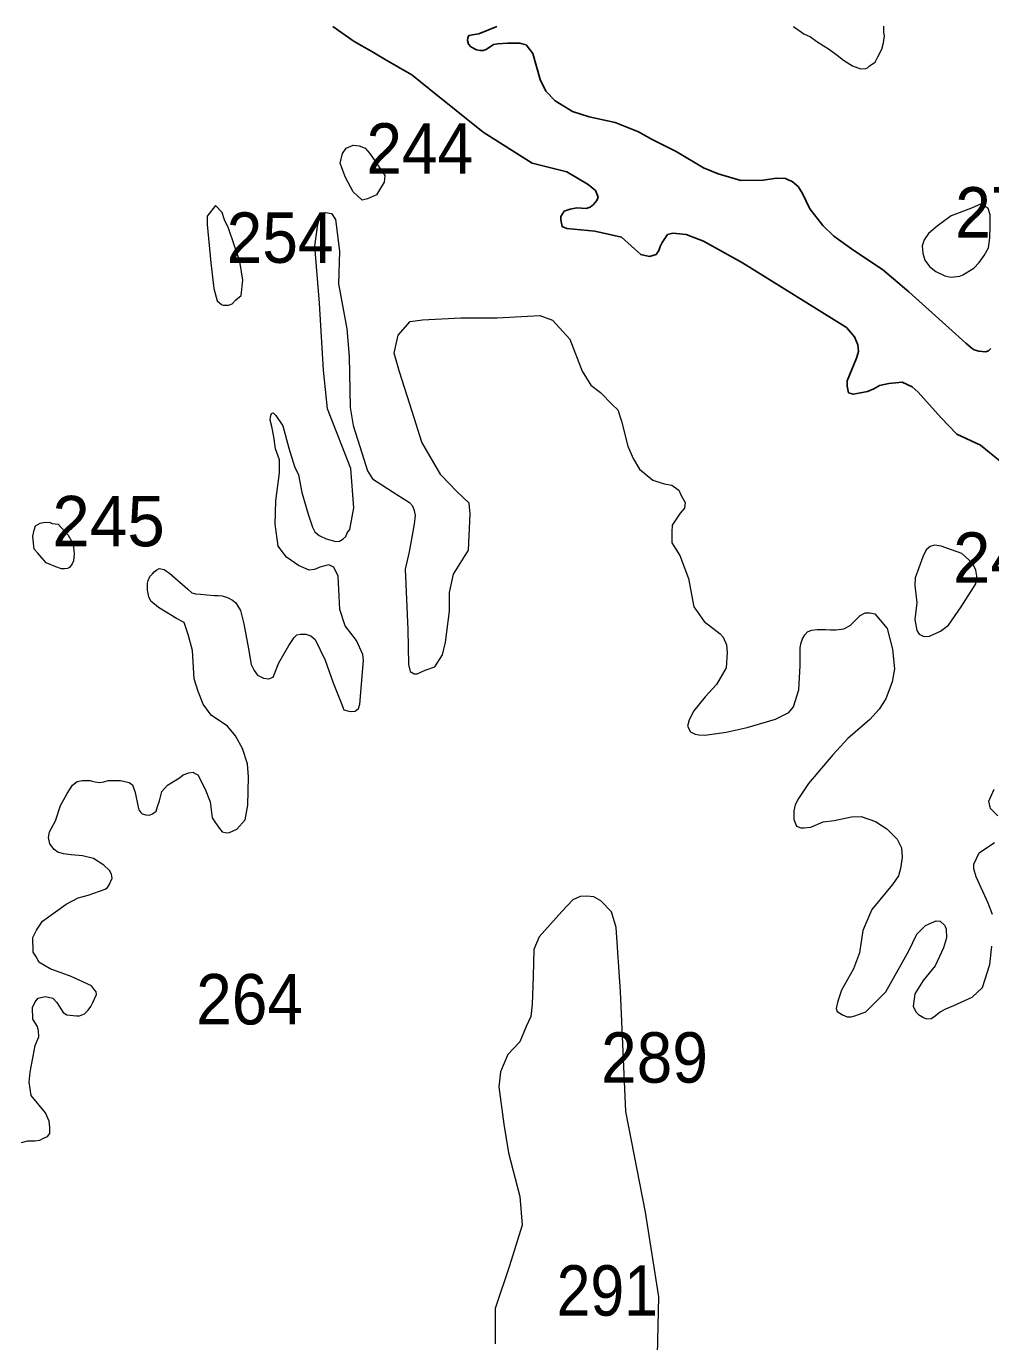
# Model space of a CAD drawing. Extents: x 445.4 to 500, y 8728.7 to 8784.
# Drawn here: x 476.604 to 479.664, y 8779.826 to 8784 of the extents above; entities that cross this region are included whole.
import ezdxf

# ---------------------------------------------------------------- set-up
doc = ezdxf.new("R2010")
doc.units = 0
doc.header["$LTSCALE"] = 0.064
doc.layers.add('1', color=7, linetype='Continuous', lineweight=25)
doc.layers.add('2', color=7, linetype='Continuous', lineweight=13)
doc.layers.add('21', color=7, linetype='Continuous')

msp = doc.modelspace()

# ---------------------------------------------------------------- linework, layer by layer
at = {"layer": '1'}
for points in [[(479.213, 8782.8368), (479.2087, 8782.858), (479.2087, 8782.8749), (479.2384, 8782.9468), (479.2447, 8782.968), (479.2426, 8782.9891), (479.232, 8783.0145), (479.2066, 8783.0441), (478.8763, 8783.2492), (478.7526, 8783.3183), (478.6975, 8783.3394), (478.6552, 8783.3436), (478.6382, 8783.3394), (478.6213, 8783.314), (478.6149, 8783.3013), (478.6107, 8783.2887), (478.6022, 8783.276), (478.6022, 8783.276), (478.5811, 8783.2696), (478.5535, 8783.276), (478.4921, 8783.3309), (478.4074, 8783.35), (478.3185, 8783.3584), (478.3037, 8783.3648), (478.2994, 8783.3859), (478.2994, 8783.3965), (478.31, 8783.4134), (478.3291, 8783.4198), (478.3503, 8783.424), (478.3799, 8783.4219), (478.3926, 8783.4261), (478.4032, 8783.4346), (478.4138, 8783.4473), (478.418, 8783.4578), (478.4095, 8783.479), (478.3863, 8783.498), (478.3185, 8783.5382), (478.2084, 8783.5657), (478.0531, 8783.6641), (477.8815, 8783.8016), (477.8265, 8783.846), (477.7418, 8783.8946), (477.6995, 8783.92), (477.6444, 8783.9517), (477.5759, 8783.999)], [(478.0963, 8783.9994), (478.0395, 8783.9765), (478.0184, 8783.9735), (478.0078, 8783.9712), (478.0041, 8783.9637), (478.0033, 8783.9546), (478.0071, 8783.9433), (478.0139, 8783.935), (478.032, 8783.9252), (478.0433, 8783.923), (478.0531, 8783.923), (478.0629, 8783.926), (478.0629, 8783.926), (478.0856, 8783.9426), (478.0999, 8783.9448), (478.1301, 8783.9471), (478.1512, 8783.9471), (478.1693, 8783.9471), (478.1769, 8783.9448), (478.1897, 8783.941), (478.2108, 8783.9139), (478.2342, 8783.831), (478.252, 8783.7943), (478.2814, 8783.7634), (478.3372, 8783.7302), (478.3893, 8783.7129), (478.4716, 8783.6948), (478.5463, 8783.6654), (478.5891, 8783.6409), (478.6653, 8783.6024), (478.7521, 8783.5512), (478.7989, 8783.5323), (478.8713, 8783.5112), (478.9415, 8783.512), (478.9844, 8783.518), (479.0131, 8783.5173), (479.0206, 8783.5135), (479.0342, 8783.5082), (479.0523, 8783.4917), (479.0667, 8783.4699), (479.09, 8783.4209), (479.1308, 8783.3682), (479.1655, 8783.3343), (479.2297, 8783.289), (479.3202, 8783.2287), (479.4037, 8783.1581), (479.5305, 8783.0435), (479.5852, 8782.9948), (479.6048, 8782.9782), (479.6108, 8782.9737), (479.6259, 8782.9691), (479.647, 8782.9676), (479.6569, 8782.9699), (479.6644, 8782.9774)], [(479.7458, 8782.5779), (479.6314, 8782.6709), (479.556, 8782.7057), (479.5052, 8782.7586), (479.4332, 8782.8389), (479.4141, 8782.8559), (479.3824, 8782.8707), (479.3612, 8782.8686), (479.34, 8782.8664), (479.3104, 8782.8601), (479.2934, 8782.8495), (479.2723, 8782.8411), (479.2511, 8782.8368), (479.2278, 8782.8326), (479.213, 8782.8368)]]:
    msp.add_lwpolyline(points, dxfattribs=at)
at = {"layer": '2'}
for points in [[(479.038, 8783.9999), (479.071, 8783.9757), (479.0921, 8783.9669), (479.1124, 8783.9524), (479.1524, 8783.9263), (479.177, 8783.9081), (479.1966, 8783.8928), (479.2257, 8783.8747), (479.2511, 8783.8652), (479.2678, 8783.8667), (479.2729, 8783.8681), (479.2794, 8783.8747), (479.2968, 8783.8863), (479.3056, 8783.903), (479.3186, 8783.9277), (479.3237, 8783.948), (479.3266, 8783.9698), (479.3244, 8783.98), (479.3245, 8784.0001)], [(477.4539, 8782.0606), (477.4621, 8782.0688), (477.4733, 8782.0719), (477.4908, 8782.0709), (477.5061, 8782.0658), (477.5205, 8782.0545), (477.5522, 8781.989), (477.5768, 8781.9174), (477.6024, 8781.8539), (477.6116, 8781.8314), (477.627, 8781.8273), (477.6362, 8781.8263), (477.6475, 8781.8273), (477.6578, 8781.8355), (477.6618, 8781.8498), (477.6677, 8781.9113), (477.6738, 8781.9891), (477.6718, 8782.0065), (477.6513, 8782.0515), (477.6154, 8782.0975), (477.5989, 8782.1494), (477.5928, 8782.2558), (477.5795, 8782.2845), (477.5631, 8782.2917), (477.5508, 8782.2886), (477.5354, 8782.2835), (477.5231, 8782.2783), (477.517, 8782.2763), (477.5016, 8782.2743), (477.4678, 8782.2896), (477.4293, 8782.3157), (477.4027, 8782.3505), (477.3934, 8782.42), (477.3955, 8782.4948), (477.4068, 8782.5828), (477.4069, 8782.6244), (477.3946, 8782.6592), (477.3885, 8782.6971), (477.3823, 8782.7308), (477.3772, 8782.7503), (477.3782, 8782.7605), (477.3813, 8782.7718), (477.3813, 8782.7718), (477.3864, 8782.7738), (477.3956, 8782.7656), (477.4171, 8782.7319), (477.4366, 8782.6612), (477.4551, 8782.6039), (477.4673, 8782.5773), (477.4776, 8782.521), (477.4982, 8782.4517), (477.5115, 8782.4108), (477.5187, 8782.3965), (477.533, 8782.3842), (477.5546, 8782.374), (477.5853, 8782.3658), (477.5976, 8782.3668), (477.6078, 8782.3729), (477.6171, 8782.3811), (477.6222, 8782.3924), (477.6304, 8782.4036), (477.6431, 8782.4726), (477.6336, 8782.5971), (477.5592, 8782.7865), (477.5467, 8782.9088), (477.5341, 8783.122), (477.5186, 8783.3025), (477.528, 8783.3652), (477.5343, 8783.3903), (477.5343, 8783.3903), (477.5531, 8783.4091), (477.572, 8783.406), (477.572, 8783.406), (477.5845, 8783.3872), (477.5971, 8783.2868), (477.5947, 8783.1826), (477.6203, 8783.0402), (477.6276, 8782.9526), (477.6313, 8782.7906), (477.6404, 8782.734), (477.6623, 8782.6664), (477.6861, 8782.5898), (477.7025, 8782.5642), (477.7793, 8782.5149), (477.8195, 8782.4894), (477.8286, 8782.4784), (477.8341, 8782.4638), (477.8378, 8782.4474), (477.8346, 8782.4204), (477.8182, 8782.3328), (477.8054, 8782.278), (477.8145, 8782.0863), (477.8164, 8781.975), (477.8218, 8781.9531), (477.8346, 8781.9458), (477.8438, 8781.9458), (477.8694, 8781.9567), (477.9004, 8781.9677), (477.9242, 8782.006), (477.9333, 8782.0462), (477.9461, 8782.1447)], [(477.9461, 8782.1447), (477.9461, 8782.2031), (477.9589, 8782.2616), (478.0064, 8782.3382), (478.0123, 8782.4527), (478.0086, 8782.4874), (477.9702, 8782.5239), (477.919, 8782.5768), (477.8587, 8782.6809), (477.8277, 8782.7776), (477.7875, 8782.9036), (477.7709, 8782.9633), (477.7836, 8783.0199), (477.822, 8783.0637), (477.8604, 8783.0692), (477.9828, 8783.0747), (478.098, 8783.0747), (478.2332, 8783.082), (478.2734, 8783.0673), (478.3282, 8783.0071), (478.3674, 8782.9056), (478.3948, 8782.8618), (478.4259, 8782.8381), (478.4624, 8782.7998), (478.4807, 8782.7833), (478.4917, 8782.7468), (478.5118, 8782.6683), (478.5296, 8782.6283), (478.5491, 8782.5953), (478.5919, 8782.5599), (478.6274, 8782.5489), (478.6519, 8782.544), (478.6739, 8782.5281), (478.6812, 8782.511), (478.6947, 8782.489), (478.6922, 8782.4707), (478.6788, 8782.4548), (478.6531, 8782.4171), (478.6519, 8782.3964), (478.6519, 8782.3609), (478.6776, 8782.3206), (478.7045, 8782.2485), (478.7216, 8782.1581), (478.7326, 8782.1435), (478.7546, 8782.1117), (478.8048, 8782.0726), (478.8146, 8782.0616), (478.8256, 8782.0372), (478.8272, 8782.013), (478.8248, 8781.9642), (478.7942, 8781.9116), (478.7575, 8781.8726), (478.722, 8781.8286), (478.7074, 8781.7993), (478.7012, 8781.7797), (478.711, 8781.7614), (478.7257, 8781.7541), (478.7379, 8781.7516), (478.7563, 8781.7504), (478.8248, 8781.7602), (478.8908, 8781.7748), (478.9813, 8781.8017), (479.0229, 8781.8225), (479.0376, 8781.8408), (479.0547, 8781.8945), (479.0596, 8781.9715), (479.0596, 8782.0265), (479.0608, 8782.0411), (479.0669, 8782.057), (479.0743, 8782.0692), (479.0828, 8782.079), (479.0951, 8782.0839), (479.1134, 8782.0863), (479.1391, 8782.0863), (479.155, 8782.0851), (479.1721, 8782.0851), (479.1978, 8782.0888), (479.2174, 8782.0986), (479.2437, 8782.1248), (479.2498, 8782.1309), (479.2657, 8782.1395), (479.2804, 8782.1395), (479.2963, 8782.1358), (479.3354, 8782.0894), (479.3526, 8782.0234), (479.3587, 8781.9611), (479.3513, 8781.92), (479.3305, 8781.8662), (479.3098, 8781.8332), (479.2804, 8781.8003), (479.2107, 8781.7404), (479.1624, 8781.6883), (479.0854, 8781.5979), (479.0536, 8781.5503), (479.0438, 8781.5295), (479.0389, 8781.5112), (479.0389, 8781.4831), (479.0475, 8781.4623), (479.0609, 8781.4574), (479.0707, 8781.4574), (479.0927, 8781.4586)], [(476.7124, 8781.528), (476.733, 8781.5656), (476.7504, 8781.5922), (476.7647, 8781.6035), (476.7811, 8781.6066), (476.7965, 8781.6076), (476.8057, 8781.6066), (476.8129, 8781.6045), (476.8221, 8781.6025), (476.8354, 8781.6004), (476.8498, 8781.6025), (476.8631, 8781.6066), (476.8733, 8781.6076), (476.8836, 8781.6076), (476.902, 8781.6076), (476.9297, 8781.6004), (476.941, 8781.5933), (476.9492, 8781.5687), (476.9584, 8781.5226), (476.9604, 8781.5145), (476.9666, 8781.5053), (476.9717, 8781.5012), (476.983, 8781.4981), (476.9942, 8781.4971), (477.0045, 8781.5012), (477.0158, 8781.5093), (477.0199, 8781.5247), (477.026, 8781.5421), (477.0332, 8781.5718), (477.0516, 8781.5922), (477.0895, 8781.6158), (477.1018, 8781.625), (477.1192, 8781.6311), (477.1326, 8781.6332), (477.1397, 8781.6291), (477.1475, 8781.6255), (477.171, 8781.5795), (477.1874, 8781.5396), (477.1936, 8781.4884), (477.2038, 8781.473), (477.2171, 8781.4546), (477.2253, 8781.4444), (477.2345, 8781.4423), (477.2407, 8781.4413), (477.2479, 8781.4423), (477.2714, 8781.4526), (477.2981, 8781.4823), (477.3063, 8781.5293), (477.3083, 8781.6184), (477.3053, 8781.66), (477.29, 8781.7081), (477.2674, 8781.7491), (477.2418, 8781.7798), (477.1906, 8781.8146), (477.1648, 8781.849), (477.1494, 8781.8899), (477.1361, 8781.9298), (477.131, 8782.0199), (477.1167, 8782.07), (477.1044, 8782.1089), (477.0798, 8782.1212), (477.0231, 8782.1557), (476.9985, 8782.1761), (476.9924, 8782.1894), (476.9883, 8782.2109), (476.9883, 8782.2334), (476.9903, 8782.2416), (476.9955, 8782.2539), (477.0047, 8782.2641), (477.0088, 8782.2693), (477.018, 8782.2754), (477.0252, 8782.2795), (477.0252, 8782.2795), (477.0405, 8782.2764), (477.0487, 8782.2713), (477.058, 8782.2652), (477.1164, 8782.214), (477.1286, 8782.2027), (477.1409, 8782.1997), (477.1563, 8782.1986), (477.1768, 8782.1966), (477.2004, 8782.1945), (477.2127, 8782.1945), (477.225, 8782.1925), (477.2424, 8782.1874), (477.2577, 8782.1792), (477.268, 8782.171), (477.2752, 8782.1598), (477.2834, 8782.1464), (477.2936, 8782.1045), (477.3084, 8782.0248), (477.3176, 8781.9747), (477.3268, 8781.9563), (477.3371, 8781.9409), (477.3371, 8781.9409), (477.3565, 8781.9317), (477.3729, 8781.9296), (477.3873, 8781.9348), (477.4047, 8781.9808), (477.4365, 8782.0351), (477.4539, 8782.0606)], [(479.6859, 8781.4955), (479.6627, 8781.5187), (479.6578, 8781.5419), (479.6749, 8781.5798)], [(476.5882, 8780.459), (476.6086, 8780.4634), (476.6203, 8780.4634), (476.6305, 8780.4634), (476.6465, 8780.4663), (476.6582, 8780.4721), (476.6713, 8780.478), (476.6786, 8780.4867), (476.6786, 8780.4955), (476.6786, 8780.5071), (476.6757, 8780.526), (476.664, 8780.5523), (476.6188, 8780.6076), (476.613, 8780.6499), (476.6159, 8780.6819), (476.632, 8780.7664), (476.6436, 8780.7941), (476.6422, 8780.813), (476.6392, 8780.8261), (476.6247, 8780.8494), (476.6233, 8780.887), (476.632, 8780.9045), (476.6408, 8780.9161), (476.6495, 8780.919), (476.6641, 8780.922), (476.6874, 8780.9161), (476.7005, 8780.903), (476.721, 8780.871), (476.7326, 8780.8637), (476.7633, 8780.8608), (476.772, 8780.8608), (476.788, 8780.8666), (476.7997, 8780.8783), (476.8085, 8780.8899), (476.8143, 8780.903), (476.8259, 8780.9285), (476.8249, 8780.9367), (476.8198, 8780.9428), (476.8106, 8780.9561), (476.746, 8780.9848), (476.6794, 8781.0094), (476.6436, 8781.0308), (476.6354, 8781.0462), (476.6251, 8781.0626), (476.6251, 8781.0769), (476.6241, 8781.0953), (476.6241, 8781.1086), (476.6354, 8781.1322), (476.6548, 8781.1608), (476.7296, 8781.2151), (476.7678, 8781.2353), (476.7995, 8781.2435), (476.8538, 8781.2619), (476.861, 8781.268), (476.8661, 8781.2762), (476.8764, 8781.2977), (476.8743, 8781.31), (476.8671, 8781.3213), (476.8497, 8781.3387), (476.8169, 8781.3591), (476.7821, 8781.3683), (476.7462, 8781.3714), (476.7217, 8781.3745), (476.7032, 8781.3796), (476.6919, 8781.3878), (476.6786, 8781.4062), (476.6745, 8781.4267), (476.6776, 8781.4441), (476.696, 8781.4789), (476.7124, 8781.528)], [(479.0927, 8781.4586), (479.1319, 8781.4757), (479.1673, 8781.4806), (479.2224, 8781.4916), (479.253, 8781.4928), (479.2982, 8781.477), (479.3337, 8781.4537), (479.3667, 8781.4208), (479.3802, 8781.3939), (479.3826, 8781.3633), (479.3777, 8781.3279), (479.3708, 8781.305), (479.3524, 8781.2769), (479.3121, 8781.2281), (479.2864, 8781.1975), (479.2583, 8781.1316), (479.2472, 8781.0607), (479.2287, 8781.01), (479.1908, 8780.9415), (479.1786, 8780.9073), (479.1737, 8780.8841), (479.1761, 8780.8744), (479.1933, 8780.8634), (479.2079, 8780.8573), (479.2214, 8780.8573), (479.2324, 8780.8609), (479.2679, 8780.8731), (479.3315, 8780.9367), (479.4036, 8781.0662), (479.4299, 8781.1194), (479.4568, 8781.1475), (479.4763, 8781.156), (479.491, 8781.1621), (479.5032, 8781.1609), (479.5032, 8781.1609), (479.5179, 8781.1475), (479.5228, 8781.1353), (479.524, 8781.1084), (479.5142, 8781.0766), (479.4873, 8781.0192), (479.4494, 8780.9728), (479.4235, 8780.9304), (479.4174, 8780.8913), (479.4223, 8780.8815), (479.4272, 8780.8717), (479.4345, 8780.8644), (479.4504, 8780.8546), (479.4602, 8780.8509), (479.4749, 8780.8522), (479.4835, 8780.8571), (479.503, 8780.8729), (479.5214, 8780.8827), (479.547, 8780.8937), (479.6045, 8780.9194), (479.6376, 8780.9499), (479.6608, 8781.0232), (479.6674, 8781.0816)], [(479.6699, 8781.1817), (479.6552, 8781.2184), (479.6173, 8781.3015), (479.6099, 8781.3271), (479.6099, 8781.3418), (479.6271, 8781.3772), (479.676, 8781.4102)], [(478.6042, 8779.6926), (478.611, 8779.9693), (478.5681, 8780.2378), (478.506, 8780.5572), (478.4892, 8780.938), (478.4749, 8781.1405), (478.4601, 8781.1904), (478.4266, 8781.2252), (478.4043, 8781.2378), (478.3819, 8781.2406), (478.361, 8781.2392), (478.3373, 8781.228), (478.3024, 8781.1918), (478.2313, 8781.111), (478.2145, 8781.0706), (478.2118, 8780.9856), (478.209, 8780.8978), (478.2048, 8780.8588), (478.1894, 8780.8267), (478.1695, 8780.7784), (478.1319, 8780.738), (478.1081, 8780.6823), (478.1026, 8780.6349), (478.1193, 8780.5165), (478.1333, 8780.4262), (478.1696, 8780.2869), (478.1766, 8780.1963), (478.1366, 8780.067), (478.0916, 8779.9319), (478.0916, 8779.8193)]]:
    msp.add_lwpolyline(points, dxfattribs=at)
for points in [[(477.6934, 8783.5967), (477.7414, 8783.5272), (477.739, 8783.5056), (477.7246, 8783.4817), (477.715, 8783.4649), (477.6862, 8783.4529), (477.6694, 8783.4481), (477.6406, 8783.4745), (477.6166, 8783.52), (477.6046, 8783.5511), (477.5998, 8783.5655), (477.607, 8783.5967), (477.619, 8783.6134), (477.6406, 8783.623), (477.6598, 8783.6206), (477.679, 8783.6134)], [(479.6339, 8783.4365), (479.6029, 8783.4236), (479.5383, 8783.3991), (479.4944, 8783.3655), (479.466, 8783.3423), (479.4531, 8783.3229), (479.4466, 8783.3036), (479.4479, 8783.2804), (479.4544, 8783.2584), (479.4699, 8783.2378), (479.4892, 8783.2223), (479.5177, 8783.2081), (479.5371, 8783.2042), (479.5655, 8783.2068), (479.5758, 8783.212), (479.6107, 8783.2326), (479.6275, 8783.2507), (479.643, 8783.2726), (479.6572, 8783.2971), (479.6611, 8783.3294), (479.6624, 8783.3642), (479.6624, 8783.4016), (479.6559, 8783.4223)], [(477.2039, 8783.4313), (477.1775, 8783.3978), (477.1775, 8783.3714), (477.1895, 8783.2492), (477.1991, 8783.1678), (477.2087, 8783.1294), (477.2231, 8783.1174), (477.2279, 8783.115), (477.2447, 8783.115), (477.2567, 8783.1198), (477.2687, 8783.1318), (477.2855, 8783.1462), (477.2903, 8783.1941), (477.2807, 8783.254), (477.2447, 8783.3595), (477.2327, 8783.3858), (477.2255, 8783.4098)], [(476.7048, 8782.4205), (476.7361, 8782.3856), (476.7518, 8782.3585), (476.7554, 8782.3259), (476.7536, 8782.3042), (476.7488, 8782.2946), (476.741, 8782.2826), (476.7343, 8782.2795), (476.7247, 8782.2789), (476.7156, 8782.2789), (476.6969, 8782.285), (476.6668, 8782.2982), (476.6396, 8782.3289), (476.6281, 8782.3416), (476.6263, 8782.3603), (476.6245, 8782.382), (476.6281, 8782.4012), (476.633, 8782.4151), (476.648, 8782.4241), (476.6637, 8782.4265), (476.6788, 8782.4253), (476.6861, 8782.4229)], [(479.4233, 8782.2255), (479.4297, 8782.1704), (479.4233, 8782.1175), (479.4297, 8782.0826), (479.4371, 8782.0709), (479.4519, 8782.0635), (479.4699, 8782.0646), (479.5049, 8782.0805), (479.5303, 8782.0995), (479.5696, 8782.1577), (479.6162, 8782.2308), (479.6194, 8782.2551), (479.6162, 8782.2742), (479.6056, 8782.2964), (479.5717, 8782.3271), (479.507, 8782.3504), (479.4858, 8782.3535), (479.472, 8782.3493), (479.4593, 8782.3387), (479.4487, 8782.3165), (479.436, 8782.2816), (479.4244, 8782.2498)]]:
    msp.add_lwpolyline(points, close=True, dxfattribs=at)

# ---------------------------------------------------------------- texts
at = {"layer": '21'}
for s, width, p in [('244', 0.95, (477.6827, 8783.5325)), ('279', 0.95, (479.5511, 8783.3299)), ('254', 0.95, (477.2393, 8783.2496)), ('264', 0.95, (477.1425, 8780.8331)), ('289', 0.95, (478.4274, 8780.6483)), ('291', 0.9, (478.2865, 8779.909))]:
    msp.add_text(s, height=0.16, dxfattribs=dict(at, width=width)).set_placement(p)
for p in [(476.6861, 8782.3502), (479.5443, 8782.2344)]:
    msp.add_text('245', height=0.16, dxfattribs=at).set_placement(p)

doc.saveas('drawing.dxf')
